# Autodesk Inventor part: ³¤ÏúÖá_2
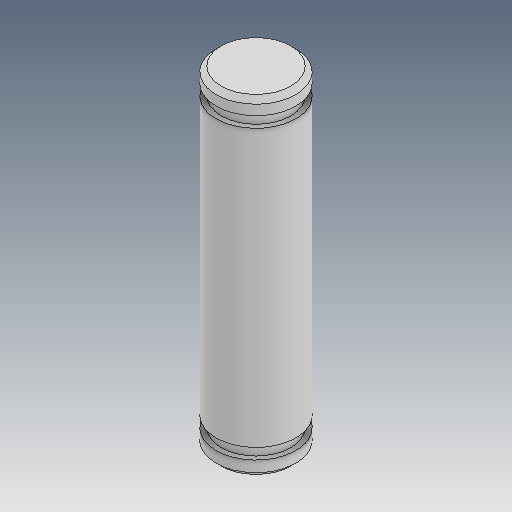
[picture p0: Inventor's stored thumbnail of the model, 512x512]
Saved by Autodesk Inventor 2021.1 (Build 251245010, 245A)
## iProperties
Created: 2019-04
Part Number: ³¤ÏúÖá_2
Material: Ogólny
Document SubType Name: Modeling
Designer: user
Density: 1 g/cm^3
Appearance: Domyślna
Author: user
Revision Number: ÈÎºÎ
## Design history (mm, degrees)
feature "ÊäÈë1"
node "Bryła1"
